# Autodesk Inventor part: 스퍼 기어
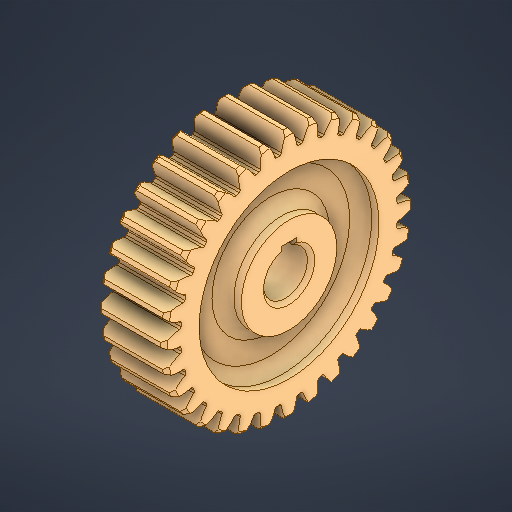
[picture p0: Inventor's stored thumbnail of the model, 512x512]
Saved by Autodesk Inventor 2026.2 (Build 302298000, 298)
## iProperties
Created: 2026-06
Part Number: 스퍼 기어
Material: 강철, 합금
Document SubType Name: Modeling
Designer: sec7
Density: 7.73 g/cm^3
Appearance: 기본값
Author: jhkim
Sending System: Autodesk Inventor 2027
Preprocessor: ST-DEVELOPER v20.1
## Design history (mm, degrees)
feature "솔리드1"
node "솔리드2"
